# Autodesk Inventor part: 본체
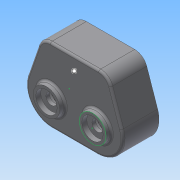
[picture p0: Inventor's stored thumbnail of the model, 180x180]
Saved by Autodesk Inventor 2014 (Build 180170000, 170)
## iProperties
Created: 2014-12
Part Number: 본체
Material: 일반
Document SubType Name: Modeling
Designer: net
Density: 1 g/cm^3
Appearance: 기본값
Author: net
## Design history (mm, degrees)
sketch "스케치1"
  geometry: L1 (-47, 36)-(47, 36); L2 (47, 36)-(66.565, -20.803); L3 (-47, 36)-(-66.565, -20.803); L4 (-32.527, -68.527)-(32.527, -68.527); L5 (0, 0)-(-32.527, -32.527); L6 (0, 0)-(0, -68.527); A1 r 36 centre (-32.527, -32.527) between (-66.565, -20.803) and (-32.527, -68.527); A2 r 36 centre (32.527, -32.527) between (32.527, -68.527) and (66.565, -20.803); A3 r 46 centre (0, 0) between (-32.527, -32.527) and (32.527, -32.527); 2 further points
  constraints: 12 end point, 6 point on circle, 3 centre point, 3 tangent, 2 midpoint, 1 coincident, 1 equal radius, 1 horizontal, 1 horizontal alignment, 1 parallel, 1 perpendicular, 1 vertical alignment
  dimensions: "d16" = 46 radius of A3; "d17" = 45 deg angle of L6 L5; "d18" = 36 radius of A1; "d19" = 94 distance of L1.start L1.end; "d20" = 36 distance from line of point (0, 0) L1
extrude "돌출1" new body sketch "스케치1" distance "d21" = 51; taper "d22" = 0 deg
fillet "모깎기1" dims "d23" = 18
fillet "모깎기2" dims "d24" = 3
sketch "스케치2"
  geometry: C1 r 20 at (-32.527, -32.527); C2 r 20 at (32.527, -32.527); A1 r 33 centre (-32.527, -32.527) between (-63.728, -21.78) and (-32.527, -65.527) reference; A2 r 33 centre (32.527, -32.527) between (32.527, -65.527) and (63.728, -21.78) reference; 1 further point
  constraints: 2 centre point, 2 coincident, 1 equal radius
  dimensions: "d25" = 40 diameter of C1
extrude "돌출2" join sketch "스케치2" distance "d26" = 7; taper "d27" = -10 deg
feature "쉘1" dims "d40" = 5
sketch "스케치5"
  geometry: C1 r 15.805 at (66.689, -63.527) reference; C2 r 15.805 at (1.635, -63.527) reference; C3 r 24 at (1.635, -63.527); C4 r 24 at (66.689, -63.527); 1 further point
  constraints: 2 centre point, 2 coincident, 1 equal radius
  dimensions: "d61" = 48 diameter of C3
extrude "돌출3" join sketch "스케치5" distance "d62" = 11; taper "d63" = 0 deg
node "작업 평면1"
sketch "스케치6"
  geometry: C1 r 18.766 at (0, 0) reference; 1 further point
sketch "스케치7"
  geometry: C1 r 15.805 at (0, 0) reference; C2 r 24 at (0, 0) reference; C3 r 15.805 at (0, 0); 1 further point
  constraints: 1 centre point, 1 coincident, 1 concentric
extrude "돌출4" join sketch "스케치7" stored distance "d65" = 10; taper "d66" = 0 deg
hole "구멍4" diameter "d69" = 15.5; stored, may be unused: countersink angle "d73" = 90 deg, drill point angle "d75" = 118 deg; dims "d67" = 10, "d68" = 10, "d70" = 6, "d71" = 30, "d72" = 7, "d74" = 21
sketch "스케치8"
  geometry: 1 further point
sketch "스케치9"
  geometry: 1 further point
fillet "모깎기3" dims "d76" = 3
hole "구멍5" diameter "d79" = 35; stored, may be unused: countersink angle "d83" = 90 deg, drill point angle "d85" = 0 deg; dims "d77" = 10, "d78" = 10, "d80" = 6, "d81" = 4, "d82" = 2, "d84" = 11
fillet "모깎기4" dims "d86" = 3
sketch "스케치10"
  geometry: C1 r 15.805 at (0, 0) reference; C2 r 24 at (0, 0) reference; C3 r 15.805 at (0, 0); 1 further point
  constraints: 1 centre point, 1 coincident, 1 concentric
extrude "돌출5" join sketch "스케치10" stored distance "d87" = 10; taper "d88" = 0 deg
fillet "모깎기5" dims "d89" = 3
sketch "스케치11"
  geometry: C1 r 24 at (34.162, -31); C2 r 24 at (66.689, -63.527) reference; 1 further point
  constraints: 1 centre point, 1 coincident, 1 equal radius
chamfer "모따기1" distance "d90" = 1; stored, may be unused: second distance "d91" = 2, angle "d92" = 45 deg
chamfer "모따기2" distance "d93" = 1; stored, may be unused: second distance "d94" = 2, angle "d95" = 45 deg
extrude "돌출6" join sketch "스케치11" distance "d96" = 11; taper "d97" = 0 deg
hole "구멍6" diameter "d100" = 35; stored, may be unused: countersink angle "d104" = 90 deg, drill point angle "d106" = 0 deg; dims "d98" = 10, "d99" = 10, "d101" = 6, "d102" = 30, "d103" = 1, "d105" = 11
sketch "스케치12"
  geometry: L1 (66.689, -94.527)-(1.635, -94.527) reference; L2 (80.615, -8.767)-(95.999, -53.432) reference; L3 (0, 0)-(68.324, 0) reference; L4 (-27.675, -53.432)-(-12.291, -8.767) reference; C1 r 24 at (66.689, -63.527) reference; C2 r 27 at (1.635, -63.527) reference; A1 r 31 centre (1.635, -63.527) between (-27.675, -53.432) and (1.635, -94.527) reference; A2 r 31 centre (66.689, -63.527) between (66.689, -94.527) and (95.999, -53.432) reference; A3 r 13 centre (68.324, -13) between (80.615, -8.767) and (68.324, 0) reference; A4 r 13 centre (0, -13) between (0, 0) and (-12.291, -8.767) reference; 1 further point
hole "구멍3" diameter "d54" = 30; stored, may be unused: countersink angle "d58" = 90 deg, drill point angle "d60" = 118 deg; dims "d50" = 10, "d51" = 10, "d55" = 6, "d56" = 30, "d57" = 7, "d59" = 7
hole "구멍2" diameter "d43" = 15.5; stored, may be unused: countersink angle "d47" = 90 deg, drill point angle "d49" = 118 deg; dims "d44" = 6, "d45" = 30, "d46" = 7, "d48" = 10, "d52" = 10, "d53" = 10
sketch "스케치4"
  geometry: L1 (34.162, 36)-(-34.162, 36) reference; L2 (-51.181, 23.862)-(-66.565, -20.803) reference; L3 (-32.527, -68.527)-(32.527, -68.527) reference; L4 (66.565, -20.803)-(51.181, 23.862) reference; L5 (-34.162, 30)-(34.162, 30); L6 (45.508, 21.908)-(60.892, -22.757); L7 (32.527, -62.527)-(-32.527, -62.527); L8 (-60.892, -22.757)-(-45.508, 21.908); A1 r 18 centre (34.162, 18) between (51.181, 23.862) and (34.162, 36) reference; A2 r 18 centre (-34.162, 18) between (-34.162, 36) and (-51.181, 23.862) reference; A3 r 36 centre (-32.527, -32.527) between (-66.565, -20.803) and (-32.527, -68.527) reference; A4 r 36 centre (32.527, -32.527) between (32.527, -68.527) and (66.565, -20.803) reference; A5 r 12 centre (34.162, 18) between (45.508, 21.908) and (34.162, 30); A6 r 30 centre (32.527, -32.527) between (32.527, -62.527) and (60.892, -22.757); A7 r 30 centre (-32.527, -32.527) between (-60.892, -22.757) and (-32.527, -62.527); A8 r 12 centre (-34.162, 18) between (-34.162, 30) and (-45.508, 21.908); 1 further point
  constraints: 8 end point, 8 point on circle, 4 centre point, 7 other
  dimensions: "d39" = 6 distance between parallel lines of L1 L5
sketch "스케치3"
  geometry: 1 further point
node "솔리드1"
mirror "대칭2"
mirror "대칭3"
mirror "대칭4"
other parameters: "d107" = 0
